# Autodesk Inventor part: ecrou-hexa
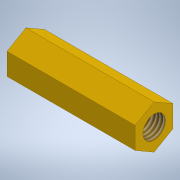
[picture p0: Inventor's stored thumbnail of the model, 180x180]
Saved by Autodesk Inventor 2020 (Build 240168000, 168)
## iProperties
Created: 2021-10
Part Number: ecrou-hexa
Material: Générique
Document SubType Name: Modeling
Designer: bruno
Density: 1 g/cm^3
Appearance: Or
Author: bruno
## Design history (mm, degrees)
sketch "Esquisse1"
  geometry: L1 (-2.887, 0)-(-1.443, 2.5); L2 (-1.443, 2.5)-(1.443, 2.5); L3 (1.443, 2.5)-(2.887, 0); L4 (2.887, 0)-(1.443, -2.5); L5 (1.443, -2.5)-(-1.443, -2.5); L6 (-1.443, -2.5)-(-2.887, 0); C1 r 1.5 at (0, 0); 2 further points
  constraints: 12 end point, 2 coincident, 1 centre point, 13 other
  dimensions: "d0" = 5 distance between parallel lines of L2 L5; "d1" = 3 diameter of C1
extrude "Extrusion1" new body sketch "Esquisse1" distance "d2" = 17; taper "d3" = 0 deg
feature "Filetage1" dims "d4" = 17, "d5" = 0
node "Solide1"
